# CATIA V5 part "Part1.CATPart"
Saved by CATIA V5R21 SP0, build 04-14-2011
Part number: Tole_inferieur
Bounding box of the stored display mesh (mm): x -106 to 106, y -175 to 175, z 0 to 64
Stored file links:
  C:\Users\zerma\Pictures\Stage Stomate\Part1.CATPart
  C:\Users\zerma\Pictures\Stage Stomate\Tole_superieur.CATPart
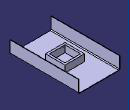
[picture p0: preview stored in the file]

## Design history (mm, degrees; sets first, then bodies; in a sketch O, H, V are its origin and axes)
SheetMetalParameters1: Thickness 2, BendRadius 4, KFactor 0.400515 {= log(min(100,max(20*SheetMetalParameters1.BendRadius,SheetMetalParameters1.Thickness)/SheetMetalParameters1.Thickness))/log(100)/2}, ReliefRadialLength 1, ReliefAxialLength 2, MinimumBendRadius 0
Body1 (main body)
  Sketch1 on xy-plane, origin (0, 0, 0), H (1, 0, 0), V (0, 1, 0)
    line L1 (-100, 175) -> (100, 175)
    line L2 (100, 175) -> (100, -175)
    line L3 (100, -175) -> (-100, -175)
    line L4 (-100, -175) -> (-100, 175)
    length L1 = 200
    length L2 = 350
    horizontal: L1 H, L3 H
    vertical: L2 V, L4 V
    symmetry: L2 L4 V, L1 L3 H
  Pad1: profile Sketch1, direction (0, 0, 1), length 2
  Recognize1: Recognize_ReferenceFace end face of Pad1, KFacteur 0.400515
  Flange1: Angle 90, Length 58, Radius 4, KFacteur 0.400515 {= log(min(100,max(20*Flange1.Radius,SheetMetalParameters1.Thickness)/SheetMetalParameters1.Thickness))/log(100)/2}, Guide edge [face of Recognize1 | face of Recognize1]
  Flange2: Angle 90, Length 58, Radius 4, KFacteur 0.400515 {= log(min(100,max(20*Flange2.Radius,SheetMetalParameters1.Thickness)/SheetMetalParameters1.Thickness))/log(100)/2}, Guide edge [face of Recognize1 | face of Recognize1]
  Sketch2 on face of Recognize1, origin (0, 0, 2), H (1, 0, 0), V (0, 1, 0)
    line L1 (50, 50) -> (50, -50)
    line L2 (50, -50) -> (-50, -50)
    line L3 (-50, -50) -> (-50, 50)
    line L4 (-50, 50) -> (50, 50)
    line L5 (40, 40) -> (40, -40)
    line L6 (40, -40) -> (-40, -40)
    line L7 (-40, -40) -> (-40, 40)
    line L8 (-40, 40) -> (40, 40)
    distance L5 L1 = 10
    vertical: L1 V, L3 V, L5 V, L7 V
    horizontal: L2 H, L4 H, L6 H, L8 H
    equidistance: L1 L3 O, L2 L4 O, L5 L7 O, L6 L8 O
  Pad2: profile Sketch2, direction (0, 0, 1), length 35
  Sketch3 on face of Pad2 from Sketch2.L2, origin (0, -50, 0), H (1, 0, 0), V (0, 0, 1)
    circle A1 centre (-30, 32) radius 1
    point P1 (-30, 32)
    circle A2 centre (-17.1, 32) radius 1
    point P2 (-17.1, 32)
    reference projected line E1 (-50, 37) -> (50, 37) from edge [face of Pad2 from Sketch2.L2 | end face of Pad2]
    reference projected line E2 (-50, 37) -> (50, 37) from edge [face of Pad2 from Sketch2.L2 | end face of Pad2]
    distance P2 E1 = 5
    distance P1 E2 = 5
    radius A2 = 1
    radius A1 = 1
    distance P2 P1 = 12.9
  Pocket1: profile Sketch3, direction (0, 1, 0), length 10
